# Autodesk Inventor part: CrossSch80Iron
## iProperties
Author: Administrator
Shininess: 57.0
PropertySet Name: _Private Model Information
Created: 2001-01
Part Number: CrossSch80Iron
Material: Steel, Mild
Document SubType Name: Modeling
Designer: Administrator
Control State: 0
Master: False
Checked Out: False
PropertySet Name: Design Tracking Control
Density: 7.86
Volumn: 25.291130211486603
Area: 122.39030542646876
PropertySet Name: Model Information
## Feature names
1. Revolution1
2. Extrusion1
3. Extrusion3
4. Extrusion2
5. Revolution2
6. Fillet1
7. Mirror1
8. Fillet2
